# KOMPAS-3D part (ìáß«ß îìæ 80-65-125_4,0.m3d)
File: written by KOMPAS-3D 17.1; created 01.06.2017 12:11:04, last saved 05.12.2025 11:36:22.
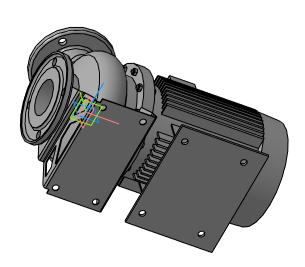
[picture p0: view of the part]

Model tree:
1. Операция без истории:4

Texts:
  ООО АДЛ ГРУПП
